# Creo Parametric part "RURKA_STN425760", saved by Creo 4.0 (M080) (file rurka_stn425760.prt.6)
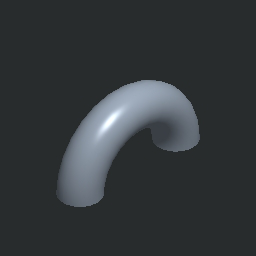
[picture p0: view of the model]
Units: millimeter Kilogram Sec (mmKs); MM, KILOGRAM, SECS
Materials in the file: OCEL_N

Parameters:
  MFG_WP_MATERIAL = "OCEL"
  NAZOV = "RURKA_STN425760"
  NORMA = "STN 42 5760"
  NAZOV_1 = "START_PART_IPM"
  PTC_MATERIAL_NAME = "OCEL_N"

Other parameters: HMOTNOST, HUSTOTA, HMOTNOST_1, HUSTOTA_1, D18

Created from: P425760.PRT

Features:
  1. datum plane "DTM1"
  2. datum plane "DTM2"
  3. datum plane "DTM3"
  4. coordinate system
  5. protrusion
  6. protrusion

Other named items: CS0

Layers: 1, 2, 3, 4, 5, 6, 7, 8, 9, 10, 11, 12, 13, 14, 15, 16, 17, 18, 19, 20, 21, 22, 23, 24, 25, 26, 27, 28, 29, 30, 31, 32

Family table entries: GENERIC, RURKA_K_31_8, RURKA_STN425760, value(d_val), value(i_val), RURKA_DK_31_8, RURKA_STN425760, RURKA_K_44_5, RURKA_STN425760, RURKA_DK_44_5, RURKA_STN425760, RURKA_K_57, RURKA_STN425760, RURKA_DK_57, RURKA_STN425760, RURKA_K_76, RURKA_STN425760, !/S, 2/i, RURKA_K_89, RURKA_STN425760, 2/n, RURKA_K_108, RURKA_STN425760, !/[, RURKA_K_133, RURKA_STN425760, RURKA_K_159, RURKA_STN425760, RURKA_K_219, RURKA_STN425760, # Pro/TABLE, [] S 92;, [] W 10;, [A] W  3;, [B] W 14;, [C] W 10;, [D] W 10;, [E] W 10;, [F] W 10;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

Surfaces: 4 torus, 1 plane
